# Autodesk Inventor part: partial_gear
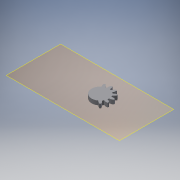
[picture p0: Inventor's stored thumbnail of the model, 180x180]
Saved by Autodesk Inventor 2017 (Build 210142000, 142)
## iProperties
Created: 2017-05
Part Number: partial_gear
Material: Silver
Document SubType Name: Modeling
Designer: 1717440
Density: 10.49 g/cm^3
Appearance: Silver
Author: 1717440
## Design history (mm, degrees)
workplane "Work Plane1"
sketch "Sketch1"
  geometry: L1 (-87.484, -3.82)-(-87.484, 3.711) reference; L2 (-87.484, -3.82)-(-66.896, -5.26) reference; L3 (-42.959, -22.554)-(20.041, -22.554) reference; L4 (20.041, 22.446)-(-42.959, 22.446) reference; L5 (-66.896, 5.151)-(-87.484, 3.711) reference; L6 (-28.459, -15.054)-(-29.709, -12.889) reference; L7 (-29.709, -12.889)-(-33.709, -12.889) reference; L8 (-33.709, -12.889)-(-34.959, -15.054) reference; L9 (-34.959, -15.054)-(-42.959, -15.054) reference; L10 (-42.959, 14.946)-(-40.459, 10.615) reference; L11 (-40.459, 10.615)-(-38.959, 10.615) reference; L12 (-38.959, 10.615)-(-36.459, 14.946) reference; L13 (-36.459, 14.946)-(-34.859, 14.946) reference; L14 (-34.859, 14.946)-(-33.609, 12.78) reference; L15 (-33.609, 12.78)-(-29.609, 12.78) reference; L16 (-29.609, 12.78)-(-28.359, 14.946) reference; L17 (-28.359, 14.946)-(-26.759, 14.946) reference; L18 (-26.759, 14.946)-(-24.259, 10.615) reference; L19 (-24.259, 10.615)-(-22.759, 10.615) reference; L20 (-22.759, 10.615)-(-20.259, 14.946) reference; L21 (-20.259, 14.946)-(-18.659, 14.946) reference; L22 (-18.659, 14.946)-(-16.159, 10.615) reference; L23 (-16.159, 10.615)-(-14.659, 10.615) reference; L24 (-14.659, 10.615)-(-12.159, 14.946) reference; L25 (-12.159, 14.946)-(-10.559, 14.946) reference; L26 (-10.559, 14.946)-(-8.059, 10.615) reference; L27 (-8.059, 10.615)-(-6.559, 10.615) reference; L28 (-6.559, 10.615)-(-4.059, 14.946) reference; L29 (-4.059, 14.946)-(-2.459, 14.946) reference; L30 (-2.459, 14.946)-(0.041, 10.615) reference; L31 (0.041, 10.615)-(1.541, 10.615) reference; L32 (1.541, 10.615)-(4.041, 14.946) reference; L33 (4.041, 14.946)-(5.641, 14.946) reference; L34 (20.041, -15.054)-(19.541, -15.054) reference; L35 (19.541, -15.054)-(17.041, -10.724) reference; L36 (17.041, -10.724)-(15.541, -10.724) reference; L37 (15.541, -10.724)-(13.041, -15.054) reference; L38 (13.041, -15.054)-(11.541, -15.054) reference; L39 (11.541, -15.054)-(10.291, -12.889) reference; L40 (10.291, -12.889)-(6.291, -12.889) reference; L41 (6.291, -12.889)-(5.041, -15.054) reference; L42 (5.041, -15.054)-(3.541, -15.054) reference; L43 (3.541, -15.054)-(1.041, -10.724) reference; L44 (1.041, -10.724)-(-0.459, -10.724) reference; L45 (-0.459, -10.724)-(-2.959, -15.054) reference; L46 (-2.959, -15.054)-(-4.459, -15.054) reference; L47 (-4.459, -15.054)-(-6.959, -10.724) reference; L48 (-6.959, -10.724)-(-8.459, -10.724) reference; L49 (-8.459, -10.724)-(-10.959, -15.054) reference; L50 (-10.959, -15.054)-(-12.459, -15.054) reference; L51 (-12.459, -15.054)-(-14.959, -10.724) reference; L52 (-14.959, -10.724)-(-16.459, -10.724) reference; L53 (-16.459, -10.724)-(-18.959, -15.054) reference; L54 (-18.959, -15.054)-(-20.459, -15.054) reference; L55 (-20.459, -15.054)-(-22.959, -10.724) reference; L56 (-22.959, -10.724)-(-24.459, -10.724) reference; L57 (-24.459, -10.724)-(-26.959, -15.054) reference; L58 (-26.959, -15.054)-(-28.459, -15.054) reference; L59 (12.785, -0.362)-(22.968, -10.545); L60 (12.785, -0.362)-(27.185, -0.362); L61 (22.968, -10.545)-(22.441, -11.071); L62 (22.441, -11.071)-(20.531, -9.969); L63 (22.441, -11.071)-(24.646, -11.071); L64 (19.91, -9.492)-(18.068, -7.65)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; C1 r 10.5 at (12.785, -0.362); A1 r 3 centre (-67.105, -8.252) between (-64.264, -7.288) and (-66.896, -5.26) reference; A2 r 22.5 centre (-42.959, -0.054) between (-64.264, -7.288) and (-42.959, -22.554) reference; A3 r 22.5 centre (20.041, -0.054) between (20.041, -22.554) and (20.041, 22.446) reference; A4 r 22.5 centre (-42.959, -0.054) between (-42.959, 22.446) and (-64.264, 7.179) reference; A5 r 3 centre (-67.105, 8.143) between (-66.896, 5.151) and (-64.264, 7.179) reference; A6 r 15 centre (-42.959, -0.054) between (-42.959, 14.946) and (-42.959, -15.054) reference; A7 r 3 centre (22.031, -7.371) between (19.91, -9.492) and (20.531, -9.969); A8 r 3 centre (19.794, -9.608) between (22.392, -8.108) and (21.915, -7.487); A9 r 3 centre (24.275, -1.976) between (23.456, -4.862) and (24.231, -4.976); A10 r 3 centre (23.411, -5.02) between (24.949, -2.444) and (24.23, -2.134); A11 r 3 centre (23.604, 3.828) between (24.296, 0.909) and (25.028, 1.187); A12 r 3 centre (24.334, 0.749) between (24.421, 3.748) and (23.642, 3.668); A13 r 3 centre (20.191, 8.569) between (22.217, 6.357) and (22.721, 6.957); A14 r 3 centre (22.328, 6.236) between (20.943, 8.897) and (20.301, 8.448); A15 r 3 centre (14.899, 11.046) between (17.747, 10.102) and (17.894, 10.871); A16 r 3 centre (17.902, 10.05) between (15.396, 11.699) and (15.055, 10.994); A17 r 3 centre (9.071, 10.629) between (12.018, 11.193) and (11.771, 11.936); A18 r 3 centre (12.179, 11.224) between (9.187, 11.442) and (9.232, 10.66); A19 r 3 centre (4.185, 7.425) between (6.484, 9.354) and (5.906, 9.883); A20 r 3 centre (6.609, 9.459) between (3.89, 8.191) and (4.311, 7.531); 8 further points
  constraints: 104 end point, 28 point on circle, 15 centre point, 14 point on line, 5 symmetric about line, 2 equal length, 2 horizontal, 2 tangent, 1 parallel, 1 perpendicular, 128 other
  dimensions: "d0" = 21 diameter of C1; "d2" = 14.4 distance of L59.start L59.end; "d3" = 45 deg angle of L59 L60; "d4" = 0.745 distance of L59.end L61.end; "d5" = 2.6 distance of L61.end point (20.189, -9.771); "d6" = 150 deg angle of L63 L62; "d7" = 3 distance of point (20.189, -9.771) L64.end; "d8" = 3 radius of A7; "d11" = 175 deg dimension on L59.start L61.end L104.start
extrude "Extrusion1" new body sketch "Sketch1" distance "d13" = 5; taper "d14" = 0 deg
sketch "Sketch2"
  geometry: C1 r 10.5 at (12.785, -0.362); A1 r 10.5 centre (12.785, -0.362) between (5.012, 6.696) and (19.139, -8.721) reference; A2 r 10.5 centre (12.785, -0.362) between (14.712, 9.959) and (12.223, 10.123) reference; 1 further point
  constraints: 1 centre point, 1 coincident, 1 concentric
extrude "Extrusion2" join sketch "Sketch2" distance "d15" = 2.5; taper "d16" = 0 deg
chamfer "Chamfer1" distance "d17" = 2; stored, may be unused: second distance "d18" = 2, angle "d19" = 45 deg
sketch "Sketch3"
  geometry: L1 (5.1, 5.1)-(-5.1, 5.1); L2 (-5.1, 5.1)-(-5.1, -5.1); L3 (-5.1, -5.1)-(5.1, -5.1); L4 (5.1, -5.1)-(5.1, 5.1); L5 (5.1, 5.1)-(-5.1, -5.1); L6 (-5.1, 5.1)-(5.1, -5.1); C1 r 10.5 at (0, 0) reference; 1 further point
  constraints: 12 end point, 2 midpoint, 2 parallel, 1 horizontal, 1 perpendicular
  dimensions: "d20" = 10.2 distance of L3.end L2.end; "d21" = 10.2 distance of L2.end L1.end
extrude "Extrusion3" cut sketch "Sketch3" distance "d22" = 5; taper "d23" = 0 deg
sketch "Sketch4"
  geometry: C1 r 5 at (-12.785, -0.362); A1 r 10.5 centre (-12.785, -0.362) between (-7.184, 8.519) and (-9.437, 9.59) reference; 1 further point
  constraints: 1 centre point, 1 coincident
  dimensions: "d24" = 10 diameter of C1
extrude "Extrusion4" join sketch "Sketch4" distance "d25" = 12; taper "d26" = 0 deg
body "Solid1"
